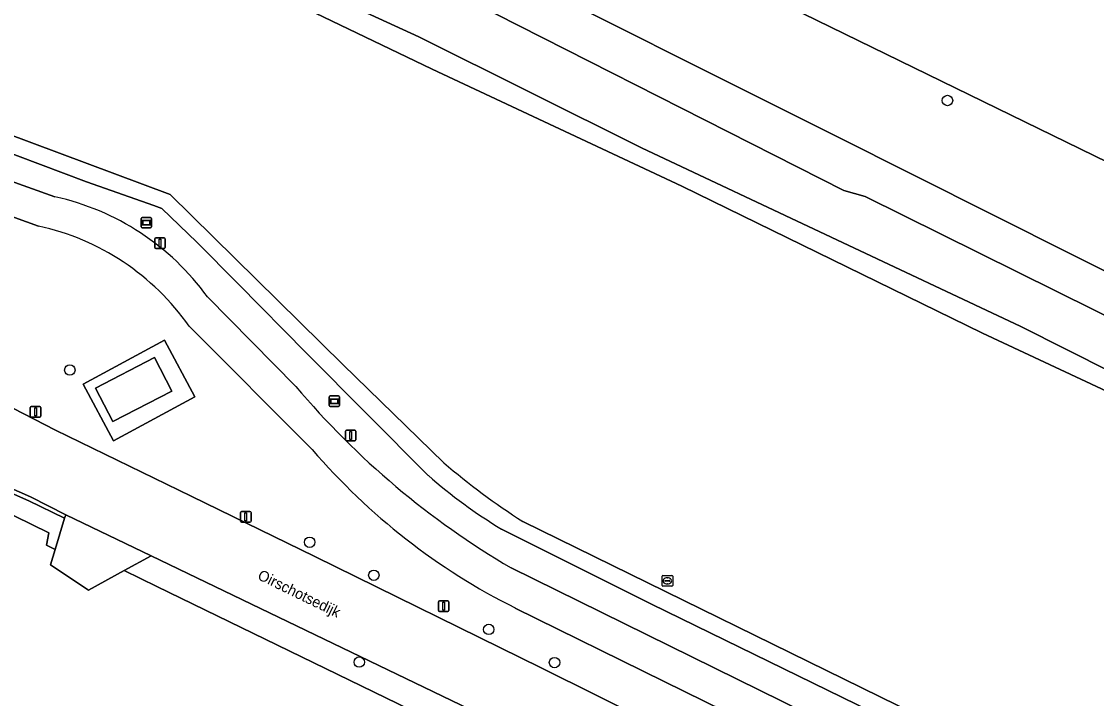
# Model space of a CAD drawing. Extents: x 156141 to 158132, y 385651 to 388333.
# Drawn here: x 156394 to 156494.8, y 386447.2 to 386510.7 of the extents above; entities that cross this region are included whole.
import ezdxf

# ---------------------------------------------------------------- set-up
doc = ezdxf.new("R2010")
doc.units = 0
for name, color, linetype in [('IMGEO_Berm_groen', 7, 'Continuous'), ('IMGEO_Boom', 7, 'Continuous'), ('IMGEO_Erf', 7, 'Continuous'), ('IMGEO_Fietspad_gesloten', 7, 'Continuous'), ('IMGEO_Groenvoorziening', 7, 'Continuous'), ('IMGEO_Hek', 7, 'Continuous'), ('IMGEO_Lichtmast', 7, 'Continuous'), ('IMGEO_Loofbos', 7, 'Continuous'), ('IMGEO_Oever', 7, 'Continuous'), ('IMGEO_Openbare_ruimte_label', 7, 'Continuous'), ('IMGEO_Pand', 7, 'Continuous'), ('IMGEO_Rijbaan_lokaal_gesloten', 7, 'Continuous'), ('IMGEO_Rijbaan_lokaal_open', 7, 'Continuous'), ('IMGEO_Rioolput', 7, 'Continuous'), ('IMGEO_Verklikker', 7, 'Continuous'), ('IMGEO_Voetpad_open', 7, 'Continuous'), ('IMGEO_Waterloop', 7, 'Continuous')]:
    doc.layers.add(name, color=color, linetype=linetype)

msp = doc.modelspace()

# ---------------------------------------------------------------- linework, layer by layer
at = {"layer": 'IMGEO_Berm_groen'}
for points in [[(156432.15, 386468.1), (156420.71, 386479.58), (156414.3, 386486.07), (156410.43, 386489.99), (156407.14, 386493.16), (156406.4, 386493.42), (156400.09, 386495.65), (156393.6, 386498.1), (156375.27, 386505.03), (156366.48, 386508.27), (156363.23, 386506.56), (156379.81, 386500.45), (156387.83, 386497.57), (156397.12, 386494.25)], [(156395.58, 386491.5), (156361.72, 386503.73), (156361.31, 386503.78)], [(156411.43, 386484.87), (156419.73, 386476.46)], [(156421.26, 386470.53), (156409.71, 386482.11)], [(156393.16, 386474.43), (156397.17, 386472.36), (156409.89, 386466.18), (156421.49, 386460.52), (156442.74, 386450.05), (156458.35, 386442.32), (156485.12, 386429.36), (156503.65, 386420.14), (156535.07, 386404.96), (156559.37, 386393.18), (156614.76, 386366.1), (156674.13, 386337.24)], [(156874.88, 386250), (156873.92, 386250.47), (156829.97, 386271.61), (156801.07, 386285.74), (156761.54, 386305.28), (156749.3, 386311.2), (156736.57, 386317.36), (156707.43, 386331.66), (156681.2, 386344.37), (156657.68, 386355.9), (156629.2, 386369.96), (156613.05, 386377.82), (156609.28, 386379.8), (156574.82, 386396.59), (156558.18, 386404.76), (156543.35, 386412.02), (156539.43, 386413.93), (156514.71, 386425.98), (156503.51, 386431.38), (156490.68, 386437.75), (156472.35, 386446.61), (156453.09, 386456.04), (156439.01, 386463.07)], [(156406.15, 386460.56), (156403.63, 386459.18), (156406.68, 386457.7), (156438.33, 386442.3), (156439.05, 386438.5), (156440.02, 386441.52)], [(156440.02, 386444.19), (156435.16, 386446.59), (156406.15, 386460.56)], [(156439.93, 386459.43), (156478.08, 386440.66), (156748.12, 386308.63), (156804.27, 386281.19), (156846.28, 386260.73), (156890.66, 386238.9), (156936.44, 386216.54), (157000.04, 386185.31), (157015.75, 386178.18)], [(157014.71, 386175.6), (157000, 386182.1), (156998.79, 386182.7), (156935.1, 386213.72), (156888.97, 386236.22), (156845.86, 386257.32), (156802.24, 386278.71), (156746.83, 386305.79), (156476.91, 386437.66), (156454.28, 386448.77), (156440.3, 386455.67)]]:
    msp.add_lwpolyline(points, dxfattribs=at)
msp.add_lwpolyline([(156410.25, 386475.48), (156402.63, 386471.36), (156399.76, 386476.67), (156407.39, 386480.79)], close=True, dxfattribs=at)
for centre, radius, start, end in [((156391.92, 386470.71), 24.11, 35.9629, 77.5317), ((156390.63, 386468.7), 23.33, 35.087, 77.7389), ((156479.24, 386526.56), 77.79, 220.0905, 239.6437), ((156467.78, 386510.52), 61.34, 220.6876, 243.3947), ((156464.24, 386504.64), 48.62, 228.7048, 238.7361)]:
    msp.add_arc(centre, radius, start, end, dxfattribs=at)
at = {"layer": 'IMGEO_Boom'}
for centre in [(156480.85, 386503.28), (156398.52, 386478), (156421.02, 386461.84), (156427.04, 386458.75), (156437.82, 386453.67), (156425.67, 386450.6), (156443.99, 386450.55)]:
    msp.add_circle(centre, 0.489, dxfattribs=at)
at = {"layer": 'IMGEO_Erf'}
for points in [[(156373.05, 386572.88), (156371.99, 386566.95), (156447.85, 386532.48), (156458.65, 386520.98), (156467.27, 386511.43), (156654.66, 386420.01)], [(156460.68, 386401.29), (156469.7, 386426.47), (156469.88, 386426.98), (156466.54, 386425.84), (156462.84, 386427.57), (156462.74, 386427.97), (156462.02, 386430.79), (156445.93, 386438.62), (156442.77, 386436.8), (156439.05, 386438.5), (156438.33, 386442.3), (156406.68, 386457.7), (156403.63, 386459.18), (156400.28, 386457.34), (156396.7, 386459.72), (156397.15, 386461.17), (156396.34, 386461.57), (156396.55, 386462.74), (156387.03, 386467.37)]]:
    msp.add_lwpolyline(points, dxfattribs=at)
at = {"layer": 'IMGEO_Fietspad_gesloten'}
for points in [[(156397.12, 386494.25), (156387.83, 386497.57), (156379.81, 386500.45), (156363.23, 386506.56), (156361.34, 386507.27), (156355.1, 386509.41), (156354.92, 386509.47), (156353.99, 386506.26), (156354.22, 386506.26), (156360.63, 386503.86), (156361.31, 386503.78), (156361.72, 386503.73), (156395.58, 386491.5)], [(156419.73, 386476.46), (156411.43, 386484.87)], [(156409.71, 386482.11), (156421.26, 386470.53)], [(156440.3, 386455.67), (156454.28, 386448.77), (156476.91, 386437.66), (156746.83, 386305.79), (156748.12, 386308.63), (156478.08, 386440.66), (156439.93, 386459.43)]]:
    msp.add_lwpolyline(points, dxfattribs=at)
for centre, radius, start, end in [((156391.92, 386470.71), 24.11, 35.9629, 77.5317), ((156390.63, 386468.7), 23.33, 35.087, 77.7389), ((156479.24, 386526.56), 77.79, 220.0905, 239.6437), ((156467.78, 386510.52), 61.34, 220.6876, 243.3947)]:
    msp.add_arc(centre, radius, start, end, dxfattribs=at)
at = {"layer": 'IMGEO_Groenvoorziening'}
msp.add_lwpolyline([(156654.66, 386420.01), (156467.27, 386511.43), (156458.65, 386520.98), (156447.85, 386532.48), (156371.99, 386566.95), (156371.97, 386566.79), (156371.25, 386562.72), (156371.29, 386561.67), (156370.42, 386551.75), (156370.85, 386550.76), (156371.71, 386549.54), (156373.54, 386548.05), (156381.06, 386542.89), (156436.29, 386517.05), (156470.28, 386500), (156500, 386485.09), (156570.45, 386449.76), (156658.9, 386407.79)], dxfattribs=at)
msp.add_lwpolyline([(156394.68, 386465.73), (156383.51, 386470.67), (156382.38, 386468.46), (156383.83, 386467.74), (156387.03, 386467.37), (156396.55, 386462.74), (156396.34, 386461.57), (156397.15, 386461.17), (156398.01, 386464.09)], close=True, dxfattribs=at)
at = {"layer": 'IMGEO_Hek'}
for points in [[(156654.66, 386420.01), (156467.27, 386511.43), (156458.65, 386520.98)], [(156406.68, 386457.7), (156438.33, 386442.3), (156439.05, 386438.5)]]:
    msp.add_lwpolyline(points, dxfattribs=at)
at = {"layer": 'IMGEO_Lichtmast'}
for p, q in [((156406.48, 386489.5), (156406.48, 386490.3)), ((156406.48, 386490.3), (156406.48, 386489.5)), ((156406.58, 386490.4), (156407.37, 386490.4)), ((156407.37, 386490.4), (156406.58, 386490.4)), ((156407.47, 386490.3), (156407.47, 386489.5)), ((156407.47, 386489.5), (156407.47, 386490.3)), ((156407.37, 386489.4), (156406.58, 386489.4)), ((156406.58, 386489.4), (156407.37, 386489.4)), ((156394.81, 386473.68), (156394.81, 386474.48)), ((156394.81, 386474.48), (156394.81, 386473.68)), ((156394.91, 386474.58), (156395.7, 386474.58)), ((156395.7, 386474.58), (156394.91, 386474.58)), ((156395.8, 386474.48), (156395.8, 386473.68)), ((156395.8, 386473.68), (156395.8, 386474.48)), ((156395.7, 386473.58), (156394.91, 386473.58)), ((156394.91, 386473.58), (156395.7, 386473.58)), ((156424.37, 386471.45), (156424.37, 386472.25)), ((156424.37, 386472.25), (156424.37, 386471.45)), ((156424.47, 386472.35), (156425.26, 386472.35)), ((156425.26, 386472.35), (156424.47, 386472.35)), ((156425.36, 386472.25), (156425.36, 386471.45)), ((156425.36, 386471.45), (156425.36, 386472.25)), ((156425.26, 386471.35), (156424.47, 386471.35)), ((156424.47, 386471.35), (156425.26, 386471.35)), ((156414.53, 386463.83), (156414.53, 386464.63)), ((156414.53, 386464.63), (156414.53, 386463.83)), ((156414.63, 386464.73), (156415.42, 386464.73)), ((156415.42, 386464.73), (156414.63, 386464.73)), ((156415.52, 386464.63), (156415.52, 386463.83)), ((156415.52, 386463.83), (156415.52, 386464.63)), ((156415.42, 386463.73), (156414.63, 386463.73)), ((156414.63, 386463.73), (156415.42, 386463.73)), ((156433.09, 386455.45), (156433.09, 386456.25)), ((156433.09, 386456.25), (156433.09, 386455.45)), ((156433.19, 386456.35), (156433.98, 386456.35)), ((156433.98, 386456.35), (156433.19, 386456.35)), ((156434.08, 386456.25), (156434.08, 386455.45)), ((156434.08, 386455.45), (156434.08, 386456.25)), ((156433.98, 386455.35), (156433.19, 386455.35)), ((156433.19, 386455.35), (156433.98, 386455.35))]:
    msp.add_line(p, q, dxfattribs=at)
for points in [[(156406.9, 386490.27), (156407.05, 386490.27), (156407.05, 386489.52), (156406.9, 386489.52), (156406.9, 386490.27)], [(156395.23, 386474.46), (156395.38, 386474.46), (156395.38, 386473.71), (156395.23, 386473.71), (156395.23, 386474.46)], [(156424.79, 386472.23), (156424.94, 386472.23), (156424.94, 386471.48), (156424.79, 386471.48), (156424.79, 386472.23)], [(156414.95, 386464.61), (156415.1, 386464.61), (156415.1, 386463.86), (156414.95, 386463.86), (156414.95, 386464.61)], [(156433.51, 386456.23), (156433.66, 386456.23), (156433.66, 386455.48), (156433.51, 386455.48), (156433.51, 386456.23)]]:
    msp.add_lwpolyline(points, dxfattribs=at)
for centre, start, end in [((156406.58, 386490.3), 90, 180), ((156406.58, 386490.3), 90, 180), ((156407.37, 386490.3), 0, 90), ((156407.37, 386490.3), 360, 90), ((156406.58, 386489.5), 180, 270), ((156406.58, 386489.5), 180, 270), ((156407.37, 386489.5), 270, 0), ((156407.37, 386489.5), 270, 0), ((156394.91, 386474.48), 90, 180), ((156394.91, 386474.48), 90, 180), ((156395.7, 386474.48), 0, 90), ((156395.7, 386474.48), 360, 90), ((156394.91, 386473.68), 180, 270), ((156394.91, 386473.68), 180, 270), ((156395.7, 386473.68), 270, 0), ((156395.7, 386473.68), 270, 0), ((156424.47, 386472.25), 90, 180), ((156424.47, 386472.25), 90, 180), ((156425.26, 386472.25), 0, 90), ((156425.26, 386472.25), 360, 90), ((156424.47, 386471.45), 180, 270), ((156424.47, 386471.45), 180, 270), ((156425.26, 386471.45), 270, 0), ((156425.26, 386471.45), 270, 0), ((156414.63, 386464.63), 90, 180), ((156414.63, 386464.63), 90, 180), ((156415.42, 386464.63), 0, 90), ((156415.42, 386464.63), 360, 90), ((156414.63, 386463.83), 180, 270), ((156414.63, 386463.83), 180, 270), ((156415.42, 386463.83), 270, 0), ((156415.42, 386463.83), 270, 0), ((156433.19, 386456.25), 90, 180), ((156433.19, 386456.25), 90, 180), ((156433.98, 386456.25), 0, 90), ((156433.98, 386456.25), 360, 90), ((156433.19, 386455.45), 180, 270), ((156433.19, 386455.45), 180, 270), ((156433.98, 386455.45), 270, 0), ((156433.98, 386455.45), 270, 0)]:
    msp.add_arc(centre, 0.1, start, end, dxfattribs=at)
at = {"layer": 'IMGEO_Loofbos'}
for points in [[(156365.25, 386539.69), (156366.42, 386509.94), (156376.51, 386506.18), (156407.94, 386494.45), (156424.13, 386478.53), (156433.61, 386469.3)], [(156508.4, 386470.1), (156484.14, 386481.46), (156455.92, 386495.25), (156432.52, 386506.23), (156410.55, 386516.78), (156394.61, 386524.34), (156380.53, 386530.67)], [(156441.01, 386463.8), (156479.51, 386444.91), (156513.81, 386428.04), (156540.12, 386415.26), (156546.07, 386412.38), (156571.02, 386399.96), (156633.35, 386369.63), (156663.58, 386354.86), (156696.62, 386338.78), (156728.15, 386323.33), (156794.45, 386290.97), (156816.86, 386279.93), (156878.47, 386250), (156993.26, 386193.78), (156997.02, 386191.93), (156998.62, 386191.17), (157000, 386190.5)]]:
    msp.add_lwpolyline(points, dxfattribs=at)
msp.add_arc((156477.52, 386520.63), 67.55, 229.4548, 237.2826, dxfattribs=at)
at = {"layer": 'IMGEO_Oever'}
for points in [[(156708.17, 386386.96), (156701.29, 386390.61), (156695.5, 386393.29), (156689.45, 386396.48), (156683.72, 386398.57), (156675.93, 386401.47), (156671.34, 386403.53), (156666.78, 386405.41), (156663.22, 386406.54), (156658.9, 386407.79), (156570.45, 386449.76), (156500, 386485.09), (156470.28, 386500), (156436.29, 386517.05), (156381.06, 386542.89), (156373.54, 386548.05), (156371.71, 386549.54), (156370.85, 386550.76), (156370.42, 386551.75), (156371.29, 386561.67), (156371.25, 386562.72), (156362.67, 386564.43), (156360.32, 386551.21)], [(156369.37, 386548.15), (156375.83, 386542.6), (156377.09, 386541.78), (156394.59, 386533.14), (156429.81, 386515.83), (156471.12, 386494.85), (156473.14, 386494.28), (156505.36, 386478.31), (156540.44, 386461.36), (156560.01, 386451.66), (156584.71, 386439.44), (156621.19, 386421.87), (156656.79, 386404.96), (156660.4, 386403.79), (156663.39, 386402.99), (156690.51, 386390.35), (156735.29, 386368.52), (156767.35, 386353.29), (156978.16, 386250), (157000, 386239.3)], [(156552.61, 386449.52), (156541.04, 386455.61), (156517.52, 386467.08), (156487.74, 386482.07), (156452.14, 386498.84), (156431.25, 386509.24), (156412.89, 386517.71), (156381.18, 386532.98), (156373.03, 386537.62), (156365.21, 386544.46)], [(156376.23, 386532.82), (156380.53, 386530.67), (156394.61, 386524.34), (156410.55, 386516.78), (156432.52, 386506.23), (156455.92, 386495.25), (156484.14, 386481.46), (156508.4, 386470.1), (156535.15, 386456.9), (156542.2, 386453.22), (156548.5, 386449.94), (156550.89, 386448.79), (156551.8, 386448.5), (156552.29, 386448.09), (156553.94, 386447.6)]]:
    msp.add_lwpolyline(points, dxfattribs=at)
at = {"layer": 'IMGEO_Pand'}
msp.add_lwpolyline([(156402.57, 386473.16), (156408.09, 386476.03), (156406.45, 386479.18), (156400.93, 386476.31)], close=True, dxfattribs=at)
at = {"layer": 'IMGEO_Rijbaan_lokaal_gesloten'}
for points in [[(156384.44, 386478.89), (156361.03, 386490.15), (156354.65, 386493.26), (156351.59, 386494.77), (156350.23, 386495.44), (156343.25, 386490.3), (156361.06, 386482.03), (156382.33, 386471.61), (156394.82, 386466.1), (156398.15, 386464.42), (156406.15, 386460.56), (156435.16, 386446.59), (156440.02, 386444.19), (156446.61, 386440.94), (156464.82, 386431.96), (156472.16, 386428.34), (156500, 386414.61), (156524.08, 386402.95), (156535.86, 386397.24), (156742.53, 386296.33)], [(156535.07, 386404.96), (156503.65, 386420.14), (156485.12, 386429.36), (156458.35, 386442.32), (156442.74, 386450.05), (156421.49, 386460.52), (156409.89, 386466.18), (156397.17, 386472.36), (156393.16, 386474.43)]]:
    msp.add_lwpolyline(points, dxfattribs=at)
at = {"layer": 'IMGEO_Rijbaan_lokaal_open'}
for points in [[(156382.33, 386471.61), (156361.06, 386482.03), (156354.65, 386481.19), (156354.57, 386480.81), (156361.03, 386481.66), (156361.64, 386481.36), (156371.65, 386476.41), (156382.16, 386471.27), (156383.51, 386470.67), (156394.68, 386465.73), (156398.01, 386464.09), (156398.15, 386464.42), (156394.82, 386466.1)], [(156406.15, 386460.56), (156398.15, 386464.42), (156398.01, 386464.09), (156397.15, 386461.17), (156396.7, 386459.72), (156400.28, 386457.34), (156403.63, 386459.18)]]:
    msp.add_lwpolyline(points, close=True, dxfattribs=at)
at = {"layer": 'IMGEO_Rioolput'}
for p, q in [((156454.08, 386457.8), (156454.08, 386458.65)), ((156454.15, 386458.72), (156455, 386458.72)), ((156454.33, 386458.22), (156454.33, 386458.23)), ((156454.77, 386458.18), (156454.37, 386458.18)), ((156454.38, 386458.27), (156454.78, 386458.27)), ((156454.56, 386458.5), (156454.59, 386458.5)), ((156454.59, 386457.94), (156454.56, 386457.94)), ((156454.82, 386458.23), (156454.82, 386458.22)), ((156455.08, 386458.65), (156455.08, 386457.8)), ((156455, 386457.72), (156454.15, 386457.72))]:
    msp.add_line(p, q, dxfattribs=at)
for points in [[(156454.08, 386457.8), (156454.08, 386458.65)], [(156454.15, 386458.72), (156455, 386458.72)], [(156455.08, 386458.65), (156455.08, 386457.8)], [(156455, 386457.72), (156454.15, 386457.72)]]:
    msp.add_lwpolyline(points, dxfattribs=at)
for centre, radius, start, end in [((156454.15, 386458.65), 0.0765, 91.552, 178.448), ((156454.15, 386458.65), 0.0765, 91.552, 178.448), ((156454.38, 386458.23), 0.0403, 85.8775, 175.7526), ((156454.37, 386458.22), 0.0366, 178.938, 274.7102), ((156454.78, 386458.22), 0.043, 264.8664, 352.4533), ((156454.78, 386458.23), 0.0386, 1.7309, 96.639), ((156455, 386458.65), 0.0765, 1.552, 88.448), ((156455, 386458.65), 0.0765, 1.552, 88.448), ((156454.15, 386457.8), 0.0765, 181.552, 268.448), ((156454.15, 386457.8), 0.0765, 181.552, 268.448), ((156455, 386457.8), 0.0765, 271.552, 358.448), ((156455, 386457.8), 0.0765, 271.552, 358.448)]:
    msp.add_arc(centre, radius, start, end, dxfattribs=at)
for centre, major_axis, ratio, start_param, end_param in [((156454.56, 386458.22), (-0.387, 0.002), 0.722429, 4.712389, 7.853982), ((156454.59, 386458.22), (-0.39, 0.002), 0.717154, 1.570796, 4.712389)]:
    msp.add_ellipse(centre, major_axis=major_axis, ratio=ratio, start_param=start_param, end_param=end_param, dxfattribs=at)
at = {"layer": 'IMGEO_Verklikker'}
for p, q in [((156405.2, 386491.43), (156405.2, 386492.22)), ((156405.2, 386492.22), (156405.2, 386491.43)), ((156405.3, 386492.32), (156406.09, 386492.32)), ((156406.09, 386492.32), (156405.3, 386492.32)), ((156406.19, 386492.22), (156406.19, 386491.43)), ((156406.19, 386491.43), (156406.19, 386492.22)), ((156406.09, 386491.33), (156405.3, 386491.33)), ((156405.3, 386491.33), (156406.09, 386491.33)), ((156422.84, 386474.67), (156422.84, 386475.47)), ((156422.84, 386475.47), (156422.84, 386474.67)), ((156422.94, 386475.57), (156423.73, 386475.57)), ((156423.73, 386475.57), (156422.94, 386475.57)), ((156423.83, 386475.47), (156423.83, 386474.67)), ((156423.83, 386474.67), (156423.83, 386475.47)), ((156423.73, 386474.57), (156422.94, 386474.57)), ((156422.94, 386474.57), (156423.73, 386474.57))]:
    msp.add_line(p, q, dxfattribs=at)
for points in [[(156405.3, 386492.06), (156406.09, 386492.06), (156406.09, 386491.59), (156405.3, 386491.59), (156405.3, 386492.06)], [(156405.36, 386491.99), (156405.36, 386491.66), (156406.02, 386491.66), (156406.02, 386491.99), (156405.36, 386491.99)], [(156422.94, 386475.3), (156423.73, 386475.3), (156423.73, 386474.83), (156422.94, 386474.83), (156422.94, 386475.3)], [(156423, 386475.23), (156423, 386474.9), (156423.66, 386474.9), (156423.66, 386475.23), (156423, 386475.23)]]:
    msp.add_lwpolyline(points, dxfattribs=at)
for centre, start, end in [((156405.3, 386492.22), 90, 180), ((156405.3, 386492.22), 90, 180), ((156406.09, 386492.22), 0, 90), ((156406.09, 386492.22), 360, 90), ((156405.3, 386491.43), 180, 270), ((156405.3, 386491.43), 180, 270), ((156406.09, 386491.43), 270, 0), ((156406.09, 386491.43), 270, 0), ((156422.94, 386475.47), 90, 180), ((156422.94, 386475.47), 90, 180), ((156423.73, 386475.47), 0, 90), ((156423.73, 386475.47), 360, 90), ((156422.94, 386474.67), 180, 270), ((156422.94, 386474.67), 180, 270), ((156423.73, 386474.67), 270, 0), ((156423.73, 386474.67), 270, 0)]:
    msp.add_arc(centre, 0.1, start, end, dxfattribs=at)
at = {"layer": 'IMGEO_Voetpad_open'}
for points in [[(156433.61, 386469.3), (156424.13, 386478.53), (156407.94, 386494.45), (156376.51, 386506.18), (156366.42, 386509.94), (156361.34, 386507.27), (156363.23, 386506.56), (156366.48, 386508.27), (156375.27, 386505.03), (156393.6, 386498.1), (156400.09, 386495.65), (156406.4, 386493.42), (156407.14, 386493.16), (156410.43, 386489.99), (156414.3, 386486.07), (156420.71, 386479.58), (156432.15, 386468.1)], [(156439.01, 386463.07), (156453.09, 386456.04), (156472.35, 386446.61), (156490.68, 386437.75), (156503.51, 386431.38), (156514.71, 386425.98), (156539.43, 386413.93), (156543.35, 386412.02), (156558.18, 386404.76), (156574.82, 386396.59), (156609.28, 386379.8), (156613.05, 386377.82), (156629.2, 386369.96)], [(157000, 386190.5), (156998.62, 386191.17), (156997.02, 386191.93), (156993.26, 386193.78), (156878.47, 386250), (156816.86, 386279.93), (156794.45, 386290.97), (156728.15, 386323.33), (156696.62, 386338.78), (156663.58, 386354.86), (156633.35, 386369.63), (156571.02, 386399.96), (156546.07, 386412.38), (156540.12, 386415.26), (156513.81, 386428.04), (156479.51, 386444.91), (156441.01, 386463.8)]]:
    msp.add_lwpolyline(points, dxfattribs=at)
for points in [[(156410.25, 386475.48), (156407.39, 386480.79), (156399.76, 386476.67), (156402.63, 386471.36)], [(156402.57, 386473.16), (156400.93, 386476.31), (156406.45, 386479.18), (156408.09, 386476.03)]]:
    msp.add_lwpolyline(points, close=True, dxfattribs=at)
for centre, radius, start, end in [((156477.52, 386520.63), 67.55, 229.4548, 237.2826), ((156464.24, 386504.64), 48.62, 228.7048, 238.7361)]:
    msp.add_arc(centre, radius, start, end, dxfattribs=at)
at = {"layer": 'IMGEO_Waterloop'}
for points in [[(156505.36, 386478.31), (156473.14, 386494.28), (156471.12, 386494.85), (156429.81, 386515.83), (156394.59, 386533.14), (156377.09, 386541.78), (156375.83, 386542.6), (156369.37, 386548.15)], [(156365.21, 386544.46), (156373.03, 386537.62), (156381.18, 386532.98), (156412.89, 386517.71), (156431.25, 386509.24), (156452.14, 386498.84), (156487.74, 386482.07), (156517.52, 386467.08), (156541.04, 386455.61), (156552.61, 386449.52)]]:
    msp.add_lwpolyline(points, dxfattribs=at)

# ---------------------------------------------------------------- texts
at = {"layer": 'IMGEO_Openbare_ruimte_label'}
msp.add_text('Oirschotsedijk', height=1, rotation=334.0243, dxfattribs=at).set_placement((156416.05, 386458.42))

doc.saveas('drawing.dxf')
